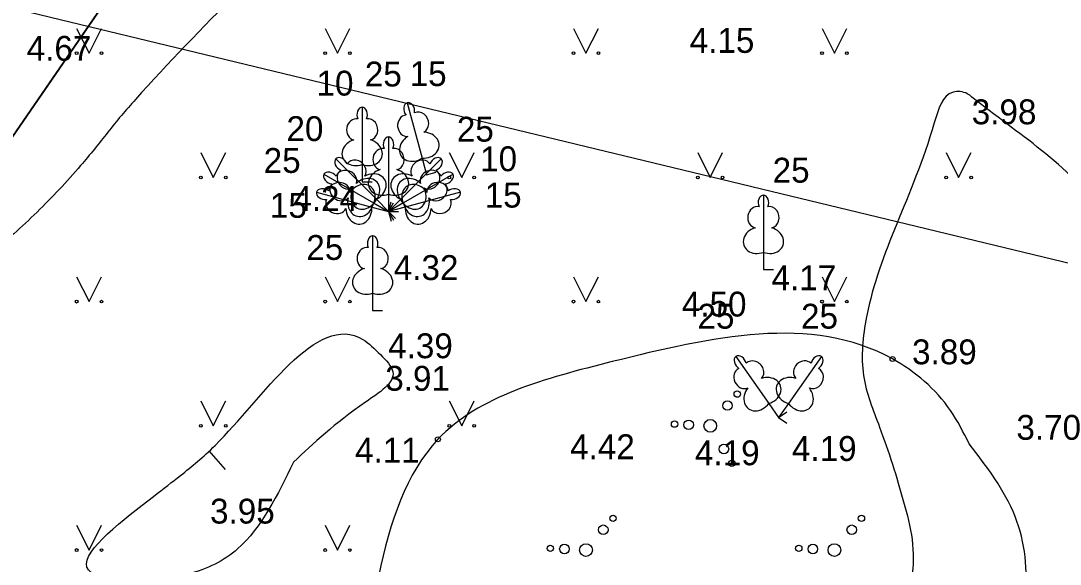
# Model space of a CAD drawing. Extents: x 519536 to 519949, y 326041 to 326519.
# Drawn here: x 519746.13 to 519767.04, y 326282.21 to 326293.15 of the extents above; entities that cross this region are included whole.
import ezdxf

# ---------------------------------------------------------------- set-up
doc = ezdxf.new("R2010")
doc.units = 0
for name, color, linetype in [('RELJ_AATZ_####_TKST_#', 7, 'Continuous'), ('RELJ_ELEM_####_####_#', 7, 'Continuous'), ('RELJ_HORZ_PAMT_####_#', 7, 'Continuous'), ('ROBZ_UZMR_####_####_#', 7, 'Continuous'), ('SAKT_VADV_PKAB_####_#', 7, 'Continuous'), ('TERT_DIAM_####_TKST_#', 7, 'Continuous'), ('TERT_ELEM_####_####_#', 7, 'Continuous'), ('TERT_KONT_####_####_#', 7, 'Continuous')]:
    doc.layers.add(name, color=color, linetype=linetype)

msp = doc.modelspace()

# ---------------------------------------------------------------- linework, layer by layer
at = {"layer": 'RELJ_ELEM_####_####_#'}
for centre in [(519763.67, 326286.346), (519754.52, 326284.729)]:
    msp.add_circle(centre, 0.05, dxfattribs=at)
at = {"layer": 'RELJ_HORZ_PAMT_####_#'}
msp.add_line((519749.912, 326284.5), (519750.24, 326284.121), dxfattribs=at)
for points in [[(519753.633, 326296.675), (519753.269, 326296.332), (519752.33, 326295.469), (519751.394, 326294.605), (519750.483, 326293.715), (519748.434, 326291.569), (519748.15, 326291.244), (519747.878, 326290.909), (519747.608, 326290.571), (519747.33, 326290.239), (519746.453, 326289.302), (519745.983, 326288.864), (519745.484, 326288.448), (519744.624, 326287.875), (519743.747, 326287.45)], [(519772.304, 326282.769), (519771.727, 326282.404), (519771.525, 326282.274), (519771.326, 326282.12), (519770.935, 326281.79), (519770.363, 326281.41), (519770.269, 326281.378), (519770.175, 326281.359), (519769.805, 326281.482), (519769.48, 326281.865), (519769.21, 326282.379), (519769.009, 326282.894), (519768.9, 326283.329), (519768.841, 326283.766), (519768.791, 326284.201), (519768.708, 326284.628), (519768.548, 326285.12), (519768.361, 326285.606), (519768.186, 326286.097), (519768.061, 326286.603), (519768.003, 326288.28), (519768.042, 326288.626), (519768.064, 326288.8), (519768.068, 326288.973), (519767.918, 326289.278), (519765.268, 326291.617), (519765.174, 326291.684), (519764.889, 326291.718), (519764.51, 326291.098), (519763.147, 326287.192), (519763.086, 326286.01), (519763.408, 326284.975), (519763.893, 326283.469), (519764.062, 326282.71), (519764.054, 326281.932), (519763.8, 326281.163), (519763.559, 326280.792), (519763.406, 326280.611), (519763.321, 326280.521), (519763.23, 326280.433), (519762.874, 326280.226), (519762.512, 326280.199), (519761.79, 326280.331), (519761.597, 326280.372), (519761.404, 326280.432), (519761.212, 326280.483), (519761.019, 326280.499), (519759.238, 326279.992), (519758.952, 326279.836), (519758.682, 326279.67), (519758.415, 326279.505), (519758.14, 326279.353), (519756.459, 326278.563), (519754.746, 326277.849), (519754.532, 326277.799), (519754.041, 326277.462), (519753.676, 326277.032), (519753.341, 326276.595), (519752.752, 326275.692), (519752.267, 326274.745), (519751.874, 326273.743), (519751.574, 326272.757), (519751.363, 326271.755), (519751.19, 326270.219)], [(519751.615, 326284.27), (519753.062, 326285.475), (519753.614, 326286.086), (519753.363, 326286.434), (519753.009, 326286.739), (519750.037, 326284.606), (519749.341, 326284.002), (519748.797, 326283.578), (519747.456, 326282.158), (519749.459, 326282.009), (519750.488, 326282.523), (519751.615, 326284.27)]]:
    msp.add_spline(points, degree=3, dxfattribs=at)
at = {"layer": 'ROBZ_UZMR_####_####_#'}
msp.add_line((519725.483, 326261.055), (519766.634, 326320.884), dxfattribs=at)
msp.add_lwpolyline([(519670.304, 326321.355), (519737.746, 326345.414), (519745.717, 326337.069), (519750.347, 326341.449), (519761.947, 326329.667), (519768.36, 326323.393), (519766.634, 326320.884), (519725.483, 326261.055)], close=True, dxfattribs=at)
at = {"layer": 'SAKT_VADV_PKAB_####_#'}
msp.add_lwpolyline([(519822.572, 326274.904), (519730.824, 326297.06)], dxfattribs=at)
at = {"layer": 'TERT_ELEM_####_####_#'}
for p, q in [((519747.25, 326293), (519747.5, 326292.5)), ((519747.5, 326292.5), (519747.75, 326293)), ((519752.25, 326293), (519752.5, 326292.5)), ((519752.5, 326292.5), (519752.75, 326293)), ((519757.25, 326293), (519757.5, 326292.5)), ((519757.5, 326292.5), (519757.75, 326293)), ((519762.25, 326293), (519762.5, 326292.5)), ((519762.5, 326292.5), (519762.75, 326293)), ((519749.75, 326290.5), (519750, 326290)), ((519750, 326290), (519750.25, 326290.5)), ((519754.202, 326290.389), (519754.292, 326290.054)), ((519754.75, 326290.5), (519755, 326290)), ((519755, 326290), (519755.25, 326290.5)), ((519759.75, 326290.5), (519760, 326290)), ((519760, 326290), (519760.25, 326290.5)), ((519764.75, 326290.5), (519765, 326290)), ((519765, 326290), (519765.25, 326290.5)), ((519752.996, 326290.259), (519752.996, 326289.912)), ((519754.292, 326290.054), (519754.485, 326290.106)), ((519752.996, 326289.912), (519753.196, 326289.912)), ((519753.225, 326289.487), (519753.526, 326289.314)), ((519753.281, 326289.559), (519753.526, 326289.314)), ((519753.526, 326289.661), (519753.526, 326289.314)), ((519753.771, 326289.559), (519753.526, 326289.314)), ((519753.526, 326289.314), (519753.578, 326289.507)), ((519753.827, 326289.487), (519753.526, 326289.314)), ((519753.526, 326289.314), (519753.626, 326289.487)), ((519753.191, 326289.404), (519753.526, 326289.314)), ((519753.526, 326289.314), (519753.667, 326289.455)), ((519753.861, 326289.404), (519753.526, 326289.314)), ((519753.526, 326289.314), (519753.726, 326289.314)), ((519753.526, 326289.314), (519753.626, 326289.141)), ((519753.526, 326289.314), (519753.578, 326289.121)), ((519753.526, 326289.314), (519753.667, 326289.173)), ((519761.071, 326288.491), (519761.071, 326288.144)), ((519761.071, 326288.144), (519761.271, 326288.144)), ((519747.25, 326288), (519747.5, 326287.5)), ((519747.5, 326287.5), (519747.75, 326288)), ((519752.25, 326288), (519752.5, 326287.5)), ((519752.5, 326287.5), (519752.75, 326288)), ((519757.25, 326288), (519757.5, 326287.5)), ((519757.5, 326287.5), (519757.75, 326288)), ((519762.25, 326288), (519762.5, 326287.5)), ((519762.5, 326287.5), (519762.75, 326288)), ((519753.207, 326287.669), (519753.207, 326287.322)), ((519753.207, 326287.322), (519753.407, 326287.322)), ((519749.75, 326285.5), (519750, 326285)), ((519750, 326285), (519750.25, 326285.5)), ((519754.75, 326285.5), (519755, 326285)), ((519755, 326285), (519755.25, 326285.5)), ((519761.178, 326285.452), (519761.377, 326285.168)), ((519761.576, 326285.452), (519761.377, 326285.168)), ((519761.377, 326285.168), (519761.541, 326285.283)), ((519761.377, 326285.168), (519761.541, 326285.053)), ((519747.25, 326283), (519747.5, 326282.5)), ((519747.5, 326282.5), (519747.75, 326283)), ((519752.25, 326283), (519752.5, 326282.5)), ((519752.5, 326282.5), (519752.75, 326283))]:
    msp.add_line(p, q, dxfattribs=at)
for points in [[(519752.996, 326291.412), (519752.996, 326290.259)], [(519753.904, 326291.503), (519754.202, 326290.389)], [(519753.086, 326291.18), (519753.085, 326291.181)], [(519754.05, 326291.302), (519754.049, 326291.302)], [(519753.526, 326290.814), (519753.526, 326289.661)], [(519753.616, 326290.582), (519753.615, 326290.583)], [(519752.465, 326290.375), (519753.281, 326289.559)], [(519754.587, 326290.375), (519753.771, 326289.559)], [(519752.693, 326290.274), (519752.692, 326290.274)], [(519754.486, 326290.147), (519754.486, 326290.148)], [(519752.227, 326290.064), (519753.225, 326289.487)], [(519752.473, 326290.025), (519752.472, 326290.025)], [(519754.825, 326290.064), (519753.827, 326289.487)], [(519752.077, 326289.702), (519753.191, 326289.404)], [(519752.325, 326289.729), (519752.324, 326289.728)], [(519754.975, 326289.702), (519753.861, 326289.404)], [(519754.669, 326289.87), (519754.669, 326289.872)], [(519754.774, 326289.556), (519754.774, 326289.557)], [(519761.071, 326289.644), (519761.071, 326288.491)], [(519761.161, 326289.412), (519761.16, 326289.413)], [(519753.207, 326288.822), (519753.207, 326287.669)], [(519753.297, 326288.59), (519753.296, 326288.591)], [(519760.517, 326286.397), (519761.178, 326285.452)], [(519762.237, 326286.397), (519761.576, 326285.452)], [(519760.723, 326286.258), (519760.722, 326286.258)], [(519762.177, 326286.155), (519762.177, 326286.156)]]:
    msp.add_lwpolyline(points, dxfattribs=at)
for centre, radius in [((519747.25, 326292.5), 0.028), ((519747.75, 326292.5), 0.0263), ((519752.25, 326292.5), 0.028), ((519752.75, 326292.5), 0.0263), ((519757.25, 326292.5), 0.028), ((519757.75, 326292.5), 0.0263), ((519762.25, 326292.5), 0.028), ((519762.75, 326292.5), 0.0263), ((519749.75, 326290), 0.028), ((519750.25, 326290), 0.0263), ((519754.75, 326290), 0.028), ((519755.25, 326290), 0.0263), ((519759.75, 326290), 0.028), ((519760.25, 326290), 0.0263), ((519764.75, 326290), 0.028), ((519765.25, 326290), 0.0263), ((519747.25, 326287.5), 0.028), ((519747.75, 326287.5), 0.0263), ((519752.25, 326287.5), 0.028), ((519752.75, 326287.5), 0.0263), ((519757.25, 326287.5), 0.028), ((519757.75, 326287.5), 0.0263), ((519762.25, 326287.5), 0.028), ((519762.75, 326287.5), 0.0263), ((519760.348, 326285.408), 0.096), ((519760.544, 326285.639), 0.064), ((519759.282, 326285.034), 0.064), ((519759.566, 326285.021), 0.096), ((519760, 326285), 0.128), ((519749.75, 326285), 0.028), ((519750.25, 326285), 0.0263), ((519754.75, 326285), 0.028), ((519755.25, 326285), 0.0263), ((519760.276, 326284.533), 0.096), ((519760.434, 326284.244), 0.064), ((519758.044, 326283.139), 0.064), ((519763.044, 326283.139), 0.064), ((519757.848, 326282.908), 0.096), ((519762.848, 326282.908), 0.096), ((519756.782, 326282.534), 0.064), ((519757.066, 326282.521), 0.096), ((519757.5, 326282.5), 0.128), ((519761.782, 326282.534), 0.064), ((519762.066, 326282.521), 0.096), ((519762.5, 326282.5), 0.128), ((519747.25, 326282.5), 0.028), ((519747.75, 326282.5), 0.0263), ((519752.25, 326282.5), 0.028), ((519752.75, 326282.5), 0.0263)]:
    msp.add_circle(centre, radius, dxfattribs=at)
for centre, major_axis, ratio, start_param, end_param in [((519752.996, 326291.262), (0, -0.15), 0.707107, 3.14537, 5.287485), ((519752.996, 326291.262), (0, -0.15), 0.707107, 0.995701, 3.137816), ((519753.943, 326291.358), (0.039, -0.145), 0.707107, 3.14537, 5.287485), ((519753.942, 326291.358), (0.039, -0.145), 0.707107, 0.995701, 3.137816), ((519752.868, 326290.967), (-0.039, -0.212), 0.861323, 3.141593, 6.283185), ((519753.124, 326290.967), (0.039, -0.212), 0.861323, 0, 3.141593), ((519753.895, 326291.04), (0.018, -0.215), 0.861323, 3.141593, 6.283185), ((519754.143, 326291.106), (0.092, -0.195), 0.861323, 0, 3.141593), ((519752.906, 326290.505), (0.307, 0.095), 0.814445, 1.570796, 4.752015), ((519753.086, 326290.505), (-0.307, 0.095), 0.814445, 1.531171, 4.712389), ((519753.526, 326290.664), (0, -0.15), 0.707107, 3.14537, 5.287485), ((519753.526, 326290.664), (0, -0.15), 0.707107, 0.995701, 3.137816), ((519754.052, 326290.604), (0.272, 0.171), 0.814445, 1.570796, 4.752015), ((519754.225, 326290.65), (-0.321, 0.012), 0.814445, 1.531171, 4.712389), ((519753.398, 326290.369), (-0.039, -0.212), 0.861323, 3.141593, 6.283185), ((519753.654, 326290.369), (0.039, -0.212), 0.861323, 0, 3.141593), ((519752.572, 326290.269), (0.106, -0.106), 0.707107, 3.14537, 5.287485), ((519752.571, 326290.268), (0.106, -0.106), 0.707107, 0.995701, 3.137816), ((519752.871, 326290.151), (0.178, -0.123), 0.861323, 6.283185, 9.424778), ((519754.181, 326290.151), (-0.178, -0.123), 0.861323, 3.141593, 6.283185), ((519754.481, 326290.268), (-0.106, -0.106), 0.707107, 3.14537, 5.287485), ((519754.48, 326290.269), (-0.106, -0.106), 0.707107, 0.995701, 3.137816), ((519752.357, 326289.989), (0.13, -0.075), 0.707107, 0.995701, 3.137816), ((519752.689, 326289.969), (0.123, -0.178), 0.861323, 3.141593, 6.283185), ((519752.676, 326289.953), (0.203, -0.073), 0.861323, 0, 3.141593), ((519753.436, 326289.907), (0.307, 0.095), 0.814445, 1.570796, 4.752015), ((519753.616, 326289.907), (-0.307, 0.095), 0.814445, 1.531171, 4.712389), ((519754.376, 326289.953), (-0.203, -0.073), 0.861323, 3.141593, 6.283185), ((519754.363, 326289.969), (-0.123, -0.178), 0.861323, 6.283185, 9.424778), ((519754.695, 326289.989), (-0.13, -0.075), 0.707107, 3.14537, 5.287485), ((519752.357, 326289.989), (0.13, -0.075), 0.707107, 3.14537, 5.287485), ((519752.54, 326289.711), (0.215, -0.018), 0.861323, 0, 3.141593), ((519753.057, 326289.688), (-0.236, -0.218), 0.814445, 1.531171, 4.712389), ((519753.17, 326289.797), (-0.284, -0.15), 0.814445, 1.531171, 4.712389), ((519753.882, 326289.797), (0.284, -0.15), 0.814445, 1.570796, 4.752015), ((519753.995, 326289.688), (0.236, -0.218), 0.814445, 1.570796, 4.752015), ((519754.512, 326289.711), (-0.215, -0.018), 0.861323, 3.141593, 6.283185), ((519754.695, 326289.989), (-0.13, -0.075), 0.707107, 0.995701, 3.137816), ((519752.222, 326289.664), (0.145, -0.039), 0.707107, 3.14537, 5.287485), ((519752.222, 326289.663), (0.145, -0.039), 0.707107, 0.995701, 3.137816), ((519752.548, 326289.73), (0.165, -0.14), 0.861323, 3.141593, 6.283185), ((519753.043, 326289.67), (0.15, 0.284), 0.814445, 1.570796, 4.752015), ((519752.976, 326289.554), (-0.171, -0.272), 0.814445, 1.531171, 4.712389), ((519754.009, 326289.67), (-0.15, 0.284), 0.814445, 1.531171, 4.712389), ((519754.076, 326289.554), (0.171, -0.272), 0.814445, 1.570796, 4.752015), ((519754.504, 326289.73), (-0.165, -0.14), 0.861323, 0, 3.141593), ((519754.83, 326289.663), (-0.145, -0.039), 0.707107, 3.14537, 5.287485), ((519754.83, 326289.664), (-0.145, -0.039), 0.707107, 0.995701, 3.137816), ((519752.474, 326289.463), (0.195, -0.092), 0.861323, 3.141593, 6.283185), ((519752.968, 326289.533), (0.071, 0.313), 0.814445, 1.570796, 4.752015), ((519754.084, 326289.533), (-0.071, 0.313), 0.814445, 1.531171, 4.712389), ((519754.578, 326289.463), (-0.195, -0.092), 0.861323, 0, 3.141593), ((519761.071, 326289.494), (0, -0.15), 0.707107, 3.14537, 5.287485), ((519761.071, 326289.494), (0, -0.15), 0.707107, 0.995701, 3.137816), ((519752.93, 326289.381), (-0.012, 0.321), 0.814445, 1.570796, 4.752015), ((519754.122, 326289.381), (0.012, 0.321), 0.814445, 1.531171, 4.712389), ((519760.943, 326289.199), (-0.039, -0.212), 0.861323, 3.141593, 6.283185), ((519761.199, 326289.199), (0.039, -0.212), 0.861323, 0, 3.141593), ((519760.981, 326288.737), (0.307, 0.095), 0.814445, 1.570796, 4.752015), ((519761.161, 326288.737), (-0.307, 0.095), 0.814445, 1.531171, 4.712389), ((519753.207, 326288.672), (0, -0.15), 0.707107, 3.14537, 5.287485), ((519753.207, 326288.672), (0, -0.15), 0.707107, 0.995701, 3.137816), ((519753.079, 326288.377), (-0.039, -0.212), 0.861323, 3.141593, 6.283185), ((519753.335, 326288.377), (0.039, -0.212), 0.861323, 0, 3.141593), ((519753.117, 326287.915), (0.307, 0.095), 0.814445, 1.570796, 4.752015), ((519753.297, 326287.915), (-0.307, 0.095), 0.814445, 1.531171, 4.712389), ((519760.603, 326286.274), (0.086, -0.123), 0.707107, 3.14537, 5.287485), ((519760.602, 326286.274), (0.086, -0.123), 0.707107, 0.995701, 3.137816), ((519762.152, 326286.274), (-0.086, -0.123), 0.707107, 3.14537, 5.287485), ((519762.151, 326286.274), (-0.086, -0.123), 0.707107, 0.995701, 3.137816), ((519760.667, 326285.959), (0.09, -0.196), 0.861323, 3.141593, 6.283185), ((519760.877, 326286.106), (0.154, -0.152), 0.861323, 6.283185, 9.424778), ((519761.877, 326286.106), (-0.154, -0.152), 0.861323, 3.141593, 6.283185), ((519762.087, 326285.959), (-0.09, -0.196), 0.861323, 6.283185, 9.424778), ((519761.11, 326285.705), (-0.306, -0.098), 0.814445, 1.531171, 4.712389), ((519761.644, 326285.705), (0.306, -0.098), 0.814445, 1.570796, 4.752015), ((519760.964, 326285.602), (0.197, 0.254), 0.814445, 1.570796, 4.752015), ((519761.79, 326285.602), (-0.197, 0.254), 0.814445, 1.531171, 4.712389)]:
    msp.add_ellipse(centre, major_axis=major_axis, ratio=ratio, start_param=start_param, end_param=end_param, dxfattribs=at)
at = {"layer": 'TERT_KONT_####_####_#'}
msp.add_spline([(519765.211, 326284.637), (519766.136, 326283.173), (519766.321, 326281.547), (519763.368, 326278.393), (519758.545, 326276.494), (519756.031, 326276.808), (519753.624, 326278.23), (519753.328, 326281.987), (519754.52, 326284.729), (519758.029, 326286.292), (519763.67, 326286.346), (519764.835, 326285.311), (519765.211, 326284.637)], degree=3, dxfattribs=at)

# ---------------------------------------------------------------- texts
at = {"layer": 'RELJ_AATZ_####_TKST_#'}
for s, p in [('4.67', (519746.244, 326292.348)), ('4.15', (519759.587, 326292.507)), (' 3.98', (519765.078, 326291.07)), (' 4.24', (519751.425, 326289.324)), ('4.32', (519753.632, 326287.935)), (' 4.17', (519761.049, 326287.73)), ('4.50', (519759.429, 326287.2)), ('4.39', (519753.519, 326286.361)), ('3.89', (519764.063, 326286.239)), (' 3.91', (519753.275, 326285.707)), (' 3.70', (519765.976, 326284.719)), ('4.11', (519752.852, 326284.261)), (' 4.42', (519756.995, 326284.329)), ('4.19', (519759.693, 326284.207)), (' 4.19', (519761.459, 326284.294)), (' 3.95', (519749.749, 326283.033))]:
    msp.add_text(s, height=0.5, dxfattribs=at).set_placement(p)
at = {"layer": 'TERT_DIAM_####_TKST_#'}
for s, p in [('25', (519753.049, 326291.83)), (' 15', (519753.766, 326291.839)), ('10', (519752.078, 326291.647)), ('20', (519751.472, 326290.732)), ('25', (519754.901, 326290.72)), ('25', (519751.014, 326290.091)), ('10', (519755.37, 326290.125)), (' 25', (519761.071, 326289.895)), ('15', (519755.461, 326289.393)), ('15', (519751.14, 326289.187)), ('25', (519751.872, 326288.34)), ('25', (519759.744, 326286.956)), ('25', (519761.828, 326286.956))]:
    msp.add_text(s, height=0.5, dxfattribs=at).set_placement(p)

doc.saveas('drawing.dxf')
